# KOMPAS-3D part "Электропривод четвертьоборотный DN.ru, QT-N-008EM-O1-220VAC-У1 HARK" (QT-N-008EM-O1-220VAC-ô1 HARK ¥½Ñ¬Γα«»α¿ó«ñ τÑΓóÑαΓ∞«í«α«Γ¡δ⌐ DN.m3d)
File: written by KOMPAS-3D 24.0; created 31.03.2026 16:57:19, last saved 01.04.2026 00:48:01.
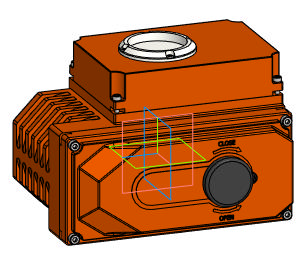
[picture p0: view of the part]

Document properties: Автор: DN.RU; Полное имя файла: D:\PROJECT CAD\DN.RU\...195\Исходники\220В\QT-N-008EM-O1-220VAC-У1 HARK Электропривод четвертьоборотный DN.ru\QT-N-008EM-O1-220VAC-У1 HARK Электропривод четвертьоборотный DN.m3d

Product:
- Body: Твердое тело1  | qty 1
    Масса: 13.49229
- Part/product: Электропривод четвертьоборотный DN.ru  | designation QT-N-008EM-O1-220VAC-У1 HARK
    Масса: 3.6
    Раздел спецификации: Прочие изделия
    Комментарий: D300-14481
    Примечание: D300-14480
    additional columns: Сталь

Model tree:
1. Твердое тело1  (labels: Твердое тело1)

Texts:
  QT-N-008EM-O1-220VAC-У1 HARK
